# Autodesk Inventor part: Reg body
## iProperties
Created: 2008-09
Part Number: Reg body
Document SubType Name: Modeling
Designer: the-dude
Density: 1 g/cm^3
Author: the-dude
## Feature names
1. Housing outline [Revolution]
2. Coil5
3. Air fitting pocket [Extrusion]
4. Solenoid hose pocket [Extrusion]
5. Air fitting holes [Extrusion]
6. Air fitting hole chamfers [Chamfer]
7. Tie screw holes thru [Extrusion]
8. Tie screw hole counterbores [Extrusion]
9. Tie screw hole array [Circular Pattern]
10. Handle locator [Extrusion]
11. Solenoid cover pocket [Extrusion]
12. Solenoid cover screw holes [Extrusion]
13. Solenoid pocket [Extrusion]
14. Solenoid wire groove [Extrusion]
15. Front pocket top chamfer [Chamfer]
16. Handle milling [Revolution]
17. Extrusion21
